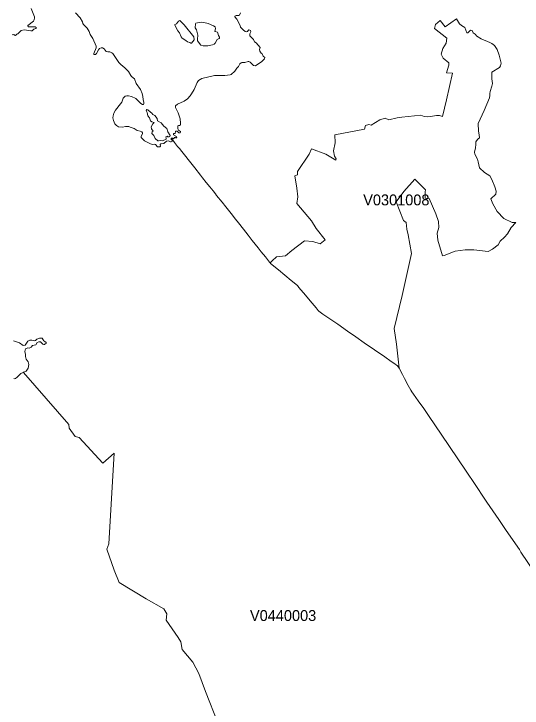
# Model space of a CAD drawing. Extents: x 369010 to 735936, y 6377141 to 6616555.
# Drawn here: x 380608 to 385285, y 6462793 to 6469182 of the extents above; entities that cross this region are included whole.
import ezdxf
from ezdxf.enums import TextEntityAlignment as Align

# ---------------------------------------------------------------- set-up
doc = ezdxf.new("R2010")
doc.units = 0
doc.header["$LTSCALE"] = 40
doc.layers.add('3', color=7, linetype='Continuous', lineweight=13)
doc.layers.add('4', color=7, linetype='Continuous')

msp = doc.modelspace()

# ---------------------------------------------------------------- linework, layer by layer
at = {"layer": '3'}
for points in [[(380767.28, 6469231.05), (380796.24, 6469153.6), (380797.9, 6469144.99), (380795.58, 6469127.78), (380787.97, 6469114.54), (380735.83, 6469074.49), (380735.5, 6469070.85), (380740.8, 6469062.9), (380804.85, 6469061.91), (380811.8, 6469057.27), (380811.8, 6469051.65), (380808.16, 6469047.67), (380790.95, 6469042.38), (380775.06, 6469026.16), (380762.48, 6469024.84), (380745.43, 6469029.47), (380701.08, 6469035.76), (380675.26, 6469029.47), (380643.48, 6468997.03), (380634.21, 6468996.04), (380622.63, 6468983.46), (380613.36, 6468986.44), (380608.4, 6468991.4), (380590.52, 6468988.09)], [(381662.33, 6468650.3), (381636.51, 6468675.79), (381629.89, 6468685.06), (381592.81, 6468716.83), (381574.61, 6468735.37), (381517.67, 6468816.13), (381509.07, 6468823.75), (381491.19, 6468832.69), (381473.32, 6468832.35), (381457.76, 6468835), (381438.89, 6468859.5), (381424.33, 6468868.1), (381412.41, 6468868.43), (381395.2, 6468862.81), (381386.6, 6468851.88), (381369.38, 6468817.79), (381357.3, 6468807.2), (381347.87, 6468808.52), (381344.06, 6468811.17), (381341.91, 6468818.12), (381364.42, 6468869.76), (381366.4, 6468883.66), (381334.13, 6468956.48), (381308.31, 6468992.73), (381299.38, 6469018.55), (381282.82, 6469049.99), (381248.73, 6469083.42), (381243.1, 6469092.03), (381237.81, 6469109.24), (381217.29, 6469145.32), (381175.25, 6469190.01)], [(382692.09, 6469190.01), (382682.82, 6469170.81), (382677.53, 6469165.51), (382652.7, 6469167.17), (382641.78, 6469159.56), (382640.78, 6469153.27), (382658.66, 6469131.75), (382689.44, 6469074.82), (382692.75, 6469059.26), (382716.25, 6469034.77), (382734.79, 6469021.19), (382750.02, 6469016.89), (382756.64, 6469021.19), (382762.6, 6469029.8), (382768.89, 6469034.1), (382777.82, 6469031.79), (382784.28, 6469029.47), (382788.41, 6469016.23), (382779.48, 6468998.19), (382779.48, 6468978.49), (382811.25, 6468946.72), (382821.52, 6468923.38), (382838.23, 6468916.76), (382874.31, 6468872.24), (382869.18, 6468853.21), (382870.34, 6468839.31), (382882.92, 6468820.11), (382891.36, 6468815.31), (382902.12, 6468793.13), (382917.67, 6468780.55), (382913.54, 6468767.97), (382890.2, 6468743.97), (382831.94, 6468704.42), (382813.41, 6468707.4), (382782.79, 6468736.69), (382768.89, 6468742.98), (382763.26, 6468743.31), (382734.13, 6468734.71), (382705, 6468734.38), (382697.72, 6468731.07), (382687.46, 6468720.8), (382675.87, 6468698.3), (382659.98, 6468681.41), (382641.45, 6468654.93), (382606.03, 6468624.48), (382599.08, 6468621.17), (382548.1, 6468613.89), (382490.01, 6468615.87), (382453.6, 6468614.88), (382337.09, 6468587.74), (382306.63, 6468569.86), (382293.06, 6468551.33), (382265.26, 6468486.12), (382242.75, 6468444.74), (382229.84, 6468426.21), (382204.68, 6468400.72), (382174.56, 6468378.21), (382112, 6468351.9), (382096.44, 6468336.01), (382094.46, 6468321.11), (382118.95, 6468270.14), (382136.83, 6468214.53), (382142.12, 6468174.81), (382140.47, 6468160.24), (382132.19, 6468155.94), (382123.92, 6468155.94), (382115.64, 6468150.64), (382116.3, 6468123.83), (382121.93, 6468110.26), (382139.64, 6468099.17), (382142.29, 6468092.88), (382138.15, 6468085.93), (382125.9, 6468087.09), (382109.35, 6468102.32), (382099.09, 6468101.98), (382096.44, 6468099.34), (382090.82, 6468081.79), (382075.92, 6468079.48), (382075.59, 6468069.22), (382104.72, 6468052.66), (382106.37, 6468045.71), (382105.05, 6468042.73), (382101.74, 6468042.07), (382102.4, 6468039.09), (382096.11, 6468040.09), (382090.82, 6468045.71), (382085.52, 6468044.72), (382078.9, 6468034.13), (382075.59, 6468032.8), (382067.31, 6468037.44)], [(382067.31, 6468037.44), (382056.56, 6468036.78), (382060.86, 6468030.82), (382086.51, 6467998.21), (382114.48, 6467962.13), (382133.35, 6467940.78), (382141.29, 6467932.01), (382178.86, 6467883.52), (382222.39, 6467827.25), (382272.21, 6467764.52), (382326.16, 6467696.33), (382344.86, 6467672.67), (382378.63, 6467629.64), (382412.22, 6467589.42), (382440.36, 6467553.34), (382461.88, 6467525.37), (382473.29, 6467511.3), (382523.94, 6467447.75), (382557.37, 6467404.88), (382606.36, 6467344.8), (382647.24, 6467292.5), (382674.22, 6467258.08), (382720.39, 6467200.15), (382763.75, 6467144.05), (382800.83, 6467096.88), (382854.45, 6467030.18), (382884.57, 6466992.45), (382922.31, 6466946.77), (382959.71, 6466898.11), (382965.83, 6466890.16), (382965.83, 6466890.16), (382984.87, 6466908.04), (383024.42, 6466944.45), (383106.18, 6466955.54), (383165.43, 6467005.69), (383281.45, 6467094.07), (383357.91, 6467087.45), (383426.43, 6467065.1), (383471.28, 6467102.01), (383389.53, 6467206.61), (383346, 6467277.94), (383210.12, 6467436.16), (383222.03, 6467496.9), (383211.61, 6467576.84), (383192.41, 6467691.7), (383217.4, 6467699.15), (383218.23, 6467730.1), (383326.47, 6467892.13), (383347.65, 6467938.8), (383478.73, 6467890.14), (383569.92, 6467835.03), (383572.9, 6467847.44), (383558.17, 6467871.77), (383548.57, 6467921.09), (383564.79, 6467995.57), (383561.81, 6468068.39), (383834.4, 6468121.18), (383842.51, 6468155.11), (383873.46, 6468164.05), (383894.81, 6468156.6), (383975.74, 6468205.92), (384025.23, 6468221.81), (384056.84, 6468207.08), (384134.79, 6468226.28), (384178.98, 6468229.92), (384352.76, 6468249.12), (384384.37, 6468238.69), (384415.65, 6468234.39), (384442.96, 6468236.54), (384496.58, 6468247.63), (384524.55, 6468246.8), (384553.35, 6468237.2), (384588.6, 6468391.29), (384643.05, 6468636.89), (384590.09, 6468639.05), (384610.61, 6468709.22), (384609.12, 6468732.06), (384556.82, 6468773.27), (384540.61, 6468811.67), (384555.34, 6468863.97), (384585.62, 6468913.78), (384592.9, 6468957.97), (384478.87, 6469046.35), (384488.47, 6469083.26), (384531.83, 6469121.16), (384577.51, 6469062.24), (384681.28, 6469136.72), (384709.92, 6469091.7), (384727.62, 6469074.82), (384757.58, 6469057.94), (384776.78, 6469008.62), (384785.55, 6469008.62), (384809.05, 6469030.63), (384824.61, 6469028.48), (384832.72, 6469007.13), (384853.24, 6468995.21), (384867.97, 6468975.35), (384907.69, 6468951.85), (384986.31, 6468919.57), (385006.83, 6468909.15)], [(385150.98, 6467156.46), (385185.24, 6467215.88), (385226.12, 6467260.73), (385193.35, 6467262.22), (385116.89, 6467299.13), (385054.99, 6467362.35), (385015.44, 6467432.36), (384997.07, 6467481.18), (385042.91, 6467522.56), (385044.4, 6467550.53), (385032.48, 6467589.42), (385006, 6467657.94), (384987.63, 6467692.53), (384938.31, 6467722.82), (384892.8, 6467766.01), (384881.71, 6467821.29), (384872.94, 6467843.3), (384849.27, 6467891.96), (384844.97, 6467908.35), (384855.23, 6467950.38), (384858.87, 6467980.67), (384859.7, 6468004.83), (384872.94, 6468026.18), (384881.71, 6468032.14), (384891.31, 6468041.74), (384889.16, 6468069.05), (384884.69, 6468103.64), (384880.22, 6468173.15), (384900.08, 6468212.87), (384935.33, 6468293.14), (384983.16, 6468410.32), (384988.46, 6468430.34), (384987.63, 6468448.88), (384990.61, 6468466.59), (385007.49, 6468515.08), (385012.62, 6468541.73), (385007.49, 6468584.43), (385006.83, 6468616.04), (385007.49, 6468646.66), (385077.5, 6468688.7), (385086.27, 6468702.6), (385092.89, 6468729.74), (385072.2, 6468802.56), (385056.15, 6468854.86), (385030.99, 6468890.28), (385006.83, 6468909.15), (384986.31, 6468919.57), (384907.69, 6468951.85), (384867.97, 6468975.35), (384853.24, 6468995.21), (384832.72, 6469007.13), (384824.61, 6469028.48), (384809.05, 6469030.63), (384785.55, 6469008.62), (384776.78, 6469008.62), (384757.58, 6469057.94), (384727.62, 6469074.82), (384709.92, 6469091.7), (384681.28, 6469136.72), (384577.51, 6469062.24), (384531.83, 6469121.16), (384488.47, 6469083.26), (384478.87, 6469046.35), (384592.9, 6468957.97), (384585.62, 6468913.78), (384555.34, 6468863.97), (384540.61, 6468811.67), (384556.82, 6468773.27), (384609.12, 6468732.06), (384610.61, 6468709.22)], [(385006.83, 6468909.15), (385030.99, 6468890.28), (385056.15, 6468854.86), (385072.2, 6468802.56), (385092.89, 6468729.74), (385086.27, 6468702.6), (385077.5, 6468688.7), (385007.49, 6468646.66), (385006.83, 6468616.04), (385007.49, 6468584.43), (385012.62, 6468541.73), (385007.49, 6468515.08), (384990.61, 6468466.59), (384987.63, 6468448.88), (384988.46, 6468430.34), (384983.16, 6468410.32), (384935.33, 6468293.14), (384900.08, 6468212.87), (384880.22, 6468173.15), (384884.69, 6468103.64), (384889.16, 6468069.05), (384891.31, 6468041.74), (384881.71, 6468032.14), (384872.94, 6468026.18), (384859.7, 6468004.83), (384858.87, 6467980.67), (384855.23, 6467950.38), (384844.97, 6467908.35), (384849.27, 6467891.96), (384872.94, 6467843.3), (384881.71, 6467821.29), (384892.8, 6467766.01), (384938.31, 6467722.82), (384987.63, 6467692.53), (385006, 6467657.94), (385032.48, 6467589.42), (385044.4, 6467550.53), (385042.91, 6467522.56), (384997.07, 6467481.18), (385015.44, 6467432.36), (385054.99, 6467362.35), (385116.89, 6467299.13), (385193.35, 6467262.22), (385226.12, 6467260.73), (385185.24, 6467215.88), (385150.98, 6467156.46), (385122.02, 6467127.5), (385082.47, 6467090.59), (385062.77, 6467054.84), (385013.62, 6467016.78), (384971.41, 6466995.76), (384841, 6467010.16), (384761.88, 6467008.83), (384669.53, 6466998.24), (384567.58, 6466958.19), (384551.86, 6466954.21), (384508.33, 6467099.36), (384503.04, 6467164.07), (384518.76, 6467216.7), (384514.95, 6467272.15), (384491.12, 6467340.83), (384430.55, 6467482.01), (384390.99, 6467485.98), (384392.64, 6467542.75), (384396.62, 6467561.12), (384298.47, 6467659.26), (384197.68, 6467546.72), (384126.02, 6467451.72), (384193.21, 6467281.42), (384219.03, 6467263.21), (384222.84, 6467199.99), (384237.4, 6467147.19), (384266.37, 6466975.56), (384180.14, 6466591.43), (384107.65, 6466286.74), (384127.34, 6466142.91), (384152.83, 6465919.81), (384182.62, 6465863.71), (384200.99, 6465827.46), (384236.08, 6465763.25), (384259.25, 6465719.55), (384268.52, 6465704.99), (384286.06, 6465681.82), (384329.42, 6465621.08), (384379.07, 6465549.91), (384429.72, 6465476.76), (384540.61, 6465312.75), (384768.84, 6464973.79), (384788.03, 6464946.15), (384834.54, 6464878.3), (384960.65, 6464687.97), (385069.23, 6464528.26), (385131.45, 6464436.9), (385180.94, 6464365.9), (385259.39, 6464251.04), (385274.28, 6464227.54), (385400.4, 6464037.37)], [(384610.61, 6468709.22), (384590.09, 6468639.05), (384643.05, 6468636.89), (384588.6, 6468391.29), (384553.35, 6468237.2), (384524.55, 6468246.8), (384496.58, 6468247.63), (384442.96, 6468236.54), (384415.65, 6468234.39), (384384.37, 6468238.69), (384352.76, 6468249.12), (384178.98, 6468229.92), (384134.79, 6468226.28), (384056.84, 6468207.08), (384025.23, 6468221.81), (383975.74, 6468205.92), (383894.81, 6468156.6), (383873.46, 6468164.05), (383842.51, 6468155.11), (383834.4, 6468121.18), (383561.81, 6468068.39), (383564.79, 6467995.57), (383548.57, 6467921.09), (383558.17, 6467871.77), (383572.9, 6467847.44), (383569.92, 6467835.03), (383478.73, 6467890.14), (383347.65, 6467938.8), (383326.47, 6467892.13), (383218.23, 6467730.1), (383217.4, 6467699.15), (383192.41, 6467691.7), (383211.61, 6467576.84), (383222.03, 6467496.9), (383210.12, 6467436.16), (383346, 6467277.94), (383389.53, 6467206.61), (383471.28, 6467102.01), (383426.43, 6467065.1), (383357.91, 6467087.45), (383281.45, 6467094.07), (383165.43, 6467005.69), (383106.18, 6466955.54), (383024.42, 6466944.45), (382984.87, 6466908.04), (382965.83, 6466890.16), (382965.83, 6466890.16), (382969.14, 6466886.03), (383043.13, 6466825.62), (383158.32, 6466728.8), (383216.74, 6466680.8), (383229.32, 6466665.08), (383291.55, 6466591.76), (383334.08, 6466541.45), (383389.19, 6466477.23), (383408.89, 6466452.24), (383412.86, 6466446.12), (383451.92, 6466418.31), (383505.21, 6466381.57), (383588.13, 6466324.8), (383677.5, 6466262.41), (383754.96, 6466209.45), (383832.08, 6466155.49), (383927.25, 6466088.96), (384020.1, 6466024.08), (384080.5, 6465982.04), (384103.01, 6465966.65), (384138.76, 6465942.65), (384152.83, 6465919.81), (384127.34, 6466142.91), (384107.65, 6466286.74), (384180.14, 6466591.43), (384266.37, 6466975.56), (384237.4, 6467147.19), (384222.84, 6467199.99), (384219.03, 6467263.21), (384193.21, 6467281.42), (384126.02, 6467451.72), (384197.68, 6467546.72), (384298.47, 6467659.26), (384396.62, 6467561.12), (384392.64, 6467542.75), (384390.99, 6467485.98), (384430.55, 6467482.01), (384491.12, 6467340.83), (384514.95, 6467272.15), (384518.76, 6467216.7), (384503.04, 6467164.07), (384508.33, 6467099.36), (384551.86, 6466954.21), (384567.58, 6466958.19), (384669.53, 6466998.24), (384761.88, 6467008.83), (384841, 6467010.16), (384971.41, 6466995.76), (385013.62, 6467016.78), (385062.77, 6467054.84), (385082.47, 6467090.59), (385122.02, 6467127.5), (385150.98, 6467156.46)], [(383389.19, 6466477.23), (383334.08, 6466541.45), (383291.55, 6466591.76), (383229.32, 6466665.08), (383216.74, 6466680.8), (383158.32, 6466728.8), (383043.13, 6466825.62), (382969.14, 6466886.03), (382965.83, 6466890.16), (382959.71, 6466898.11), (382922.31, 6466946.77), (382884.57, 6466992.45), (382854.45, 6467030.18), (382800.83, 6467096.88), (382763.75, 6467144.05), (382720.39, 6467200.15), (382674.22, 6467258.08), (382647.24, 6467292.5), (382606.36, 6467344.8), (382557.37, 6467404.88), (382523.94, 6467447.75), (382473.29, 6467511.3), (382461.88, 6467525.37), (382440.36, 6467553.34), (382412.22, 6467589.42), (382378.63, 6467629.64), (382344.86, 6467672.67), (382326.16, 6467696.33), (382272.21, 6467764.52), (382222.39, 6467827.25), (382178.86, 6467883.52), (382141.29, 6467932.01), (382133.35, 6467940.78), (382114.48, 6467962.13), (382086.51, 6467998.21), (382060.86, 6468030.82), (382056.56, 6468036.78), (382054.4, 6468031.48), (382055.07, 6468024.2), (382066.32, 6468015.59), (382066.98, 6468011.62), (382054.74, 6468005.33), (382047.78, 6468005.33), (382029.25, 6468014.27), (382013.36, 6468011.95), (381986.88, 6467990.44), (381960.07, 6467985.8), (381955.1, 6467979.51), (381956.43, 6467964.95), (381955.1, 6467959.98), (381951.79, 6467958), (381930.44, 6467957.67), (381911.08, 6467979.18), (381902.97, 6467982.49), (381884.43, 6467981.17), (381865.9, 6467985.47), (381810.29, 6468014.6), (381790.43, 6468030.49), (381779.83, 6468045.05), (381777.85, 6468057.63), (381792.41, 6468077.82), (381792.41, 6468087.75), (381785.46, 6468096.36), (381771.23, 6468102.65), (381743.42, 6468109.27), (381715.62, 6468125.49), (381678.54, 6468140.71), (381663.98, 6468144.69), (381634.85, 6468144.02), (381608.37, 6468139.72), (381571.3, 6468142.7), (381552.1, 6468153.29), (381536.21, 6468169.18), (381524.96, 6468199.3), (381519.33, 6468226.44), (381520.65, 6468243.66), (381527.94, 6468269.48), (381542.17, 6468296.29), (381589.83, 6468352.89), (381599.76, 6468370.1), (381614, 6468406.02), (381633.2, 6468424.88), (381646.11, 6468428.86), (381663.32, 6468428.52), (381689.14, 6468422.24), (381728.53, 6468402.71), (381776.52, 6468356.86), (381791.42, 6468347.59), (381799.03, 6468347.92), (381804.33, 6468356.86), (381803.67, 6468366.13), (381796.05, 6468393.77), (381793.74, 6468421.57), (381788.11, 6468449.38), (381773.87, 6468485.13), (381734.49, 6468540.74), (381717.93, 6468585.09), (381690.46, 6468606.28), (381683.18, 6468614.88), (381662.33, 6468650.3)], [(385400.4, 6464037.37), (385274.28, 6464227.54), (385259.39, 6464251.04), (385180.94, 6464365.9), (385131.45, 6464436.9), (385069.23, 6464528.26), (384960.65, 6464687.97), (384834.54, 6464878.3), (384788.03, 6464946.15), (384768.84, 6464973.79), (384540.61, 6465312.75), (384429.72, 6465476.76), (384379.07, 6465549.91), (384329.42, 6465621.08), (384286.06, 6465681.82), (384268.52, 6465704.99), (384259.25, 6465719.55), (384236.08, 6465763.25), (384200.99, 6465827.46), (384182.62, 6465863.71), (384152.83, 6465919.81), (384138.76, 6465942.65), (384103.01, 6465966.65), (384080.5, 6465982.04), (384020.1, 6466024.08), (383927.25, 6466088.96), (383832.08, 6466155.49), (383754.96, 6466209.45), (383677.5, 6466262.41), (383588.13, 6466324.8), (383505.21, 6466381.57), (383451.92, 6466418.31), (383412.86, 6466446.12), (383408.89, 6466452.24), (383389.19, 6466477.23)], [(380605.58, 6466174.19), (380641.33, 6466160.79), (380659.37, 6466155.16), (380693.96, 6466131.33), (380711.17, 6466132.32), (380736.83, 6466169.39), (380753.05, 6466180.32), (380773.9, 6466180.32), (380796.24, 6466172.21), (380805.51, 6466177.01), (380820.24, 6466188.43), (380843.58, 6466197.36), (380866.75, 6466197.86), (380876.35, 6466181.31), (380884.79, 6466174.19), (380891.08, 6466165.59), (380904.32, 6466158.47), (380903.82, 6466148.04), (380896.21, 6466146.06), (380890.58, 6466140.43), (380884.79, 6466137.95), (380875.35, 6466141.26), (380851.19, 6466162.28), (380836.46, 6466163.27), (380822.56, 6466155.99), (380809.32, 6466137.45), (380780.35, 6466129.84), (380767.45, 6466114.28), (380749.41, 6466106.67), (380735.17, 6466107.17), (380715.15, 6466099.06), (380709.02, 6466073.9), (380714.65, 6466046.26), (380714.32, 6466027.23), (380720.94, 6466003.89), (380739.97, 6465979.73), (380745.6, 6465955.56), (380738.98, 6465920.81), (380720.94, 6465893.17), (380695.78, 6465883.57)], [(382485.87, 6462658.56), (382370.35, 6462944.88), (382309.61, 6463110.22), (382254.5, 6463215.31), (382157.35, 6463333.65), (382142.95, 6463403.16), (382120.61, 6463442.72), (382007.57, 6463601.43), (382015.51, 6463659.2), (381986.55, 6463706.53), (381825.02, 6463797.23), (381577.09, 6463949.32), (381529.76, 6464063.69), (381461.57, 6464254.18), (381481.76, 6464304.5), (381531.25, 6465138.64), (381427.48, 6465047.94), (381209.51, 6465283.12), (381171.44, 6465291.07), (381116.16, 6465367.69), (381114.84, 6465403.11), (380696.77, 6465882.41), (380695.78, 6465883.57), (380693.8, 6465882.74), (380670.96, 6465870.83), (380656.23, 6465858.08), (380638.68, 6465837.56), (380623.46, 6465826.64), (380614.02, 6465823.82), (380606.41, 6465827.13)], [(380695.78, 6465883.57), (380696.77, 6465882.41), (381114.84, 6465403.11), (381116.16, 6465367.69), (381171.44, 6465291.07), (381209.51, 6465283.12), (381427.48, 6465047.94), (381531.25, 6465138.64), (381481.76, 6464304.5), (381461.57, 6464254.18), (381529.76, 6464063.69), (381577.09, 6463949.32), (381825.02, 6463797.23), (381986.55, 6463706.53), (382015.51, 6463659.2), (382007.57, 6463601.43), (382120.61, 6463442.72), (382142.95, 6463403.16), (382157.35, 6463333.65), (382254.5, 6463215.31), (382309.61, 6463110.22), (382370.35, 6462944.88), (382485.87, 6462658.56)]]:
    msp.add_lwpolyline(points, dxfattribs=at)
for points in [[(382176.05, 6469082.27), (382135.83, 6469120.5), (382121.27, 6469114.21), (382103.72, 6469091.04), (382088.83, 6469082.76), (382088.17, 6469078.46), (382114.98, 6469025.5), (382132.19, 6469007.62), (382146.42, 6468971.54), (382157.68, 6468958.96), (382190.78, 6468936.29), (382204.02, 6468923.38), (382226.2, 6468918.42), (382237.12, 6468912.79), (382242.75, 6468913.45), (382265.59, 6468942.58), (382262.61, 6468971.87)], [(382395.34, 6469094.68), (382355.62, 6469103.28), (382331.79, 6469104.61), (382282.14, 6469097.33), (382277.83, 6469089.38), (382274.52, 6469054.29), (382288.1, 6469036.09), (382301.01, 6468987.43), (382296.04, 6468949.2), (382298.36, 6468933.81), (382329.14, 6468894.58), (382349, 6468886.64), (382392.69, 6468887.63), (382436.39, 6468896.57), (382450.29, 6468903.19), (382458.9, 6468910.8), (382479.42, 6468944.73), (382496.96, 6468954), (382500.77, 6468959.3), (382500.44, 6468968.23), (382489.68, 6468983.13), (382486.04, 6469005.64), (382481.4, 6469012.26), (382460.22, 6469018.88), (382456.91, 6469022.85), (382462.21, 6469045.03), (382459.56, 6469061.91), (382444.99, 6469072.17)], [(381904.62, 6468246.3), (381886.75, 6468256.57), (381876.82, 6468268.81), (381864.24, 6468276.43), (381840.74, 6468300.26), (381831.14, 6468300.59), (381826.51, 6468292.31), (381827.17, 6468286.36), (381835.44, 6468274.11), (381840.41, 6468244.32), (381855.3, 6468224.46), (381864.9, 6468196.65), (381876.49, 6468189.37), (381897.34, 6468183.74), (381896.02, 6468177.79), (381886.09, 6468171.17), (381871.85, 6468141.71), (381873.51, 6468124.16), (381888.73, 6468102.65), (381880.79, 6468095.36), (381877.81, 6468081.13), (381895.69, 6468061.27), (381906.61, 6468036.45), (381932.59, 6468014.93), (381937.89, 6468012.94), (381960.07, 6468017.91), (381976.29, 6468013.27), (382007.73, 6468030.16), (382010.21, 6468036.61), (382006.41, 6468050.35), (382017.66, 6468055.64), (382024.28, 6468049.35), (382037.19, 6468049.35), (382043.48, 6468053.66), (382044.81, 6468061.27), (382024.28, 6468096.69), (382014.35, 6468126.81), (381988.2, 6468149.98), (381963.05, 6468180.1), (381928.62, 6468198.97), (381927.46, 6468219.16)]]:
    msp.add_lwpolyline(points, close=True, dxfattribs=at)

# ---------------------------------------------------------------- texts
at = {"layer": '4'}
for s, p in [('V0301008', (384127.26, 6467419.76)), ('V0440003', (383085.09, 6463594.78))]:
    msp.add_text(s, height=100, dxfattribs=at).set_placement(p, align=Align.CENTER)

doc.saveas('drawing.dxf')
